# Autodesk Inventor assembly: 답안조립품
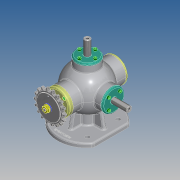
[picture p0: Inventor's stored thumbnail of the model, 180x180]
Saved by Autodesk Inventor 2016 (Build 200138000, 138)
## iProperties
Created: 2016-03
Part Number: 답안조립품
Document SubType Name: Assembly
Designer: Administrator
Author: Administrator
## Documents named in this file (17)
- D:\360308V1005\360308V1005\답안조립품.iam
- D:\360308V1005\360308V1005\본체.ipt
- D:\360308V1005\360308V1005\축.ipt
- D:\360308V1005\360308V1005\키 3 x 3 x 12.ipt
- D:\360308V1005\360308V1005\베어링- 6202.ipt
- D:\360308V1005\360308V1005\뒤커버.ipt
- D:\360308V1005\360308V1005\앞커버.ipt
- D:\360308V1005\360308V1005\오일실.ipt
- D:\360308V1005\360308V1005\본체커버.ipt
- D:\360308V1005\360308V1005\슬라이드.ipt
- D:\360308V1005\360308V1005\스프링.ipt
- D:\360308V1005\360308V1005\스프링-2.ipt
- D:\360308V1005\360308V1005\슬라이드 커버.ipt
- D:\360308V1005\360308V1005\볼트 M4x0.7.ipt
- D:\360308V1005\360308V1005\너트-M8x1.ipt
- D:\360308V1005\360308V1005\스프로킷.ipt
- D:\360308V1005\360308V1005\와셔 8x17.ipt
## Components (17 placed, 1 different names)
1. M4x0.7x12:1
2. M4x0.7x12:2
3. M4x0.7x12:3
4. M4x0.7x12:4
5. M4x0.7x12:5
6. M4x0.7x12:6
7. M4x0.7x12:7
8. M4x0.7x12:8
9. M4x0.7x12:9
10. M4x0.7x12:10
11. M4x0.7x12:11
12. M4x0.7x12:12
13. M4x0.7x12:13
14. M4x0.7x12:14
15. M4x0.7x12:15
16. M4x0.7x12:16
17. M4x0.7x12:17
